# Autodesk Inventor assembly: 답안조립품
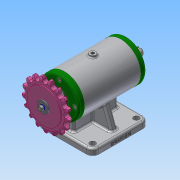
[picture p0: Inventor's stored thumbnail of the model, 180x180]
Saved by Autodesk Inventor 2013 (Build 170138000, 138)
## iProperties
Created: 2019-06
Part Number: 답안조립품
Document SubType Name: Assembly
Designer: Administrator
Author: Administrator
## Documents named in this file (11)
- C:\Users\Administrator\Desktop\490604V1021\답안조립품.iam
- C:\Users\Administrator\Desktop\490604V1021\본체.ipt
- C:\Users\Administrator\Desktop\490604V1021\베어링 6203.ipt
- C:\Users\Administrator\Desktop\490604V1021\볼트 M4.ipt
- C:\Users\Administrator\Desktop\490604V1021\스프로킷.ipt
- C:\Users\Administrator\Desktop\490604V1021\스프링와셔.ipt
- C:\Users\Administrator\Desktop\490604V1021\오일 실 17 30 5.ipt
- C:\Users\Administrator\Desktop\490604V1021\축.ipt
- C:\Users\Administrator\Desktop\490604V1021\커버.ipt
- C:\Users\Administrator\Desktop\490604V1021\키 4x4x12.ipt
- C:\Users\Administrator\Desktop\490604V1021\평와셔.ipt
